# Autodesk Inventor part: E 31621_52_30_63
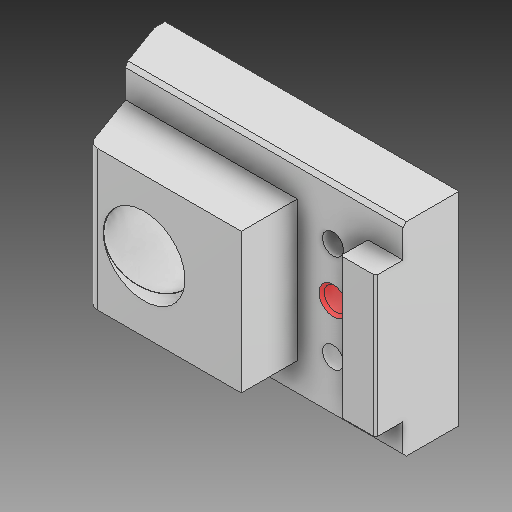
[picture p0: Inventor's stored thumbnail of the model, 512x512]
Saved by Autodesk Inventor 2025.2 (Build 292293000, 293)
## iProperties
Created: 2025-03
Part Number: E 31621_52_30_63
Material: Všeobecné
Document SubType Name: Modeling
Designer: Patrik
Density: 1 g/cm^3
Appearance: Výchozí
Mass: 11.8053 g
Surface Area: 48.6504 cm^2
Volume: 11.8053 cm^3
Author: Patrik
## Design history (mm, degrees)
feature "Base1"
node "Těleso1"
